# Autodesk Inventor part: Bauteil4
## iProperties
Created: 2005-04
Part Number: Bauteil4
Cost Center: 0,1 kg
Checked By: Schilling
Material: Stahl (hohe Festigk., niedr. Legier.)
Document SubType Name: Modeling
Designer: Nützel
Authority: 7308,56 mm^3
Manufacturer: Standard
Standards Organization: Custom
SaveDate: 2005-04-24
SaveTime: 14:12
TotalMass: 0,1 kg
TotalVolume: 7308,56 mm^3
Author: Nützel
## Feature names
1. Extrusion1
2. Extrusion2
